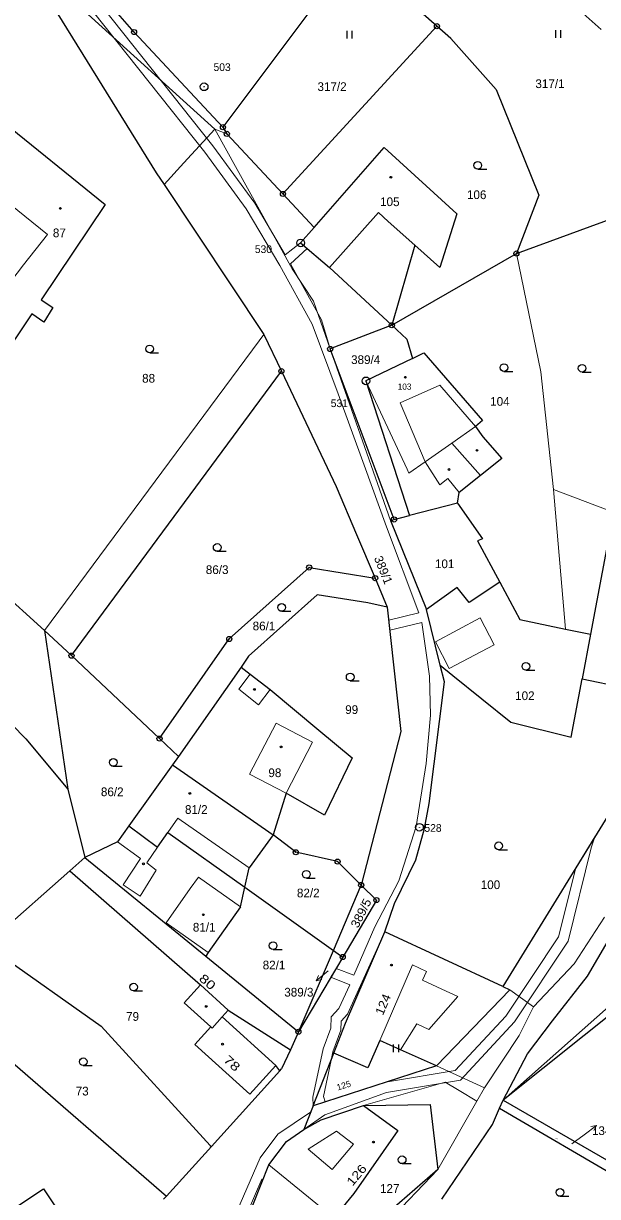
# Model space of a CAD drawing. Extents: x -504006 to -501322, y -1128098 to -1124665.
# Drawn here: x -502691.9 to -502579.9, y -1126531.9 to -1126303.1 of the extents above; entities that cross this region are included whole.
import ezdxf
from ezdxf.enums import TextEntityAlignment as Align

# ---------------------------------------------------------------- set-up
doc = ezdxf.new("R2010")
doc.units = 0
doc.header["$LTSCALE"] = 0.68
for name, color, linetype, lineweight in [('1', 7, 'Continuous', 25), ('13', 7, 'Continuous', 13), ('3', 7, 'Continuous', 25), ('4', 7, 'Continuous', 13), ('5', 7, 'Continuous', 25), ('7', 7, 'Continuous', 13), ('8', 7, 'Continuous', 25)]:
    doc.layers.add(name, color=color, linetype=linetype, lineweight=lineweight)
doc.layers.add('2', color=7, linetype='Continuous')

msp = doc.modelspace()

# ---------------------------------------------------------------- linework, layer by layer
at = {"layer": '1'}
for p, q in [((-502627.56, -1126289.31), (-502653, -1126323.36)), ((-502611.25, -1126303.66), (-502627.56, -1126289.31)), ((-502595.09, -1126290.13), (-502579.17, -1126304.31)), ((-502687.49, -1126297.6), (-502666, -1126332.24)), ((-502670.34, -1126304.81), (-502677, -1126297.14)), ((-502611.25, -1126303.66), (-502641.29, -1126336.37)), ((-502608.55, -1126306.04), (-502611.25, -1126303.66)), ((-502653, -1126323.36), (-502670.34, -1126304.81)), ((-502608.55, -1126306.04), (-502599.68, -1126316.02)), ((-502599.68, -1126316.02), (-502591.34, -1126336.62)), ((-502696.91, -1126321.52), (-502675.99, -1126338.4)), ((-502653, -1126323.36), (-502652.25, -1126324.66)), ((-502641.29, -1126336.37), (-502652.25, -1126324.66)), ((-502635.19, -1126342.89), (-502621.54, -1126327.31)), ((-502621.54, -1126327.31), (-502607.35, -1126340.25)), ((-502666, -1126332.24), (-502664.48, -1126334.52)), ((-502664.48, -1126334.52), (-502644.99, -1126363.8)), ((-502641.29, -1126336.37), (-502635.19, -1126342.89)), ((-502591.34, -1126336.62), (-502595.74, -1126348)), ((-502675.99, -1126338.4), (-502688.46, -1126357.01)), ((-502595.74, -1126348), (-502570.14, -1126338.62)), ((-502607.35, -1126340.25), (-502610.7, -1126350.73)), ((-502635.19, -1126342.89), (-502637.84, -1126345.92)), ((-502637.84, -1126345.92), (-502632.22, -1126350.69)), ((-502615.54, -1126346.39), (-502620.04, -1126361.99)), ((-502620.04, -1126361.99), (-502595.74, -1126348)), ((-502610.7, -1126350.73), (-502615.54, -1126346.39)), ((-502632.22, -1126350.69), (-502620.04, -1126361.99)), ((-502688.46, -1126357.01), (-502686.2, -1126358.53)), ((-502686.2, -1126358.53), (-502687.95, -1126361.35)), ((-502690.31, -1126359.77), (-502697.31, -1126370.22)), ((-502687.95, -1126361.35), (-502690.31, -1126359.77)), ((-502644.99, -1126363.8), (-502641.6, -1126370.94)), ((-502620.04, -1126361.99), (-502632.07, -1126366.61)), ((-502620.04, -1126361.99), (-502617.13, -1126364.69)), ((-502617.13, -1126364.69), (-502616.03, -1126368.48)), ((-502619.62, -1126399.86), (-502632.07, -1126366.61)), ((-502616.03, -1126368.48), (-502625.1, -1126372.83)), ((-502616.03, -1126368.48), (-502613.77, -1126367.39)), ((-502613.77, -1126367.39), (-502602.38, -1126380.59)), ((-502682.55, -1126426.42), (-502641.6, -1126370.94)), ((-502641.6, -1126370.94), (-502630.93, -1126393.44)), ((-502625.1, -1126372.83), (-502616.58, -1126399.09)), ((-502602.38, -1126380.59), (-502603.73, -1126381.76)), ((-502603.73, -1126381.76), (-502602.27, -1126383.76)), ((-502602.27, -1126383.76), (-502598.57, -1126387.94)), ((-502598.57, -1126387.94), (-502602.76, -1126391.31)), ((-502602.76, -1126391.31), (-502606.88, -1126394.62)), ((-502630.93, -1126393.44), (-502626.91, -1126402.76)), ((-502607.25, -1126396.69), (-502606.88, -1126394.62)), ((-502607.25, -1126396.69), (-502616.58, -1126399.09)), ((-502607.25, -1126396.69), (-502602.37, -1126403.63)), ((-502620.31, -1126400.04), (-502619.62, -1126399.86)), ((-502620.31, -1126400.04), (-502613.3, -1126417.44)), ((-502619.62, -1126399.86), (-502616.58, -1126399.09)), ((-502626.91, -1126402.76), (-502623.31, -1126411.3)), ((-502602.37, -1126403.63), (-502603.3, -1126404)), ((-502603.3, -1126404), (-502598.97, -1126412.1)), ((-502577.79, -1126403.55), (-502581.3, -1126422.25)), ((-502705.53, -1126405.59), (-502687.79, -1126421.49)), ((-502651.77, -1126423.17), (-502636.18, -1126409.22)), ((-502636.18, -1126409.22), (-502623.31, -1126411.3)), ((-502623.31, -1126411.3), (-502620.93, -1126416.93)), ((-502598.97, -1126412.1), (-502604.96, -1126416.04)), ((-502598.97, -1126412.1), (-502595.08, -1126419.38)), ((-502634.61, -1126414.54), (-502647.99, -1126426.52)), ((-502624.74, -1126416.13), (-502634.61, -1126414.54)), ((-502607.33, -1126413.1), (-502613.3, -1126417.44)), ((-502604.96, -1126416.04), (-502607.33, -1126413.1)), ((-502620.93, -1126416.93), (-502624.74, -1126416.13)), ((-502716.32, -1126417.67), (-502691.44, -1126442.61)), ((-502620.93, -1126416.93), (-502618.28, -1126441.22)), ((-502610.61, -1126428.26), (-502613.3, -1126417.44)), ((-502595.08, -1126419.38), (-502586.19, -1126421.23)), ((-502586.19, -1126421.23), (-502581.3, -1126422.25)), ((-502687.79, -1126421.49), (-502682.55, -1126426.42)), ((-502687.79, -1126421.49), (-502683.27, -1126452.45)), ((-502665.37, -1126442.59), (-502651.77, -1126423.17)), ((-502581.3, -1126422.25), (-502582.93, -1126430.94)), ((-502665.37, -1126442.59), (-502682.55, -1126426.42)), ((-502647.99, -1126426.52), (-502649.47, -1126428.64)), ((-502610.61, -1126428.26), (-502608.12, -1126430.26)), ((-502609.8, -1126431.52), (-502610.61, -1126428.26)), ((-502649.47, -1126428.64), (-502661.67, -1126446.07)), ((-502649.47, -1126428.64), (-502647.66, -1126430.04)), ((-502647.66, -1126430.04), (-502643.77, -1126433.05)), ((-502608.12, -1126430.26), (-502596.85, -1126439.37)), ((-502612.77, -1126455.27), (-502609.8, -1126431.52)), ((-502585.05, -1126442.3), (-502582.93, -1126430.94)), ((-502582.93, -1126430.94), (-502571.03, -1126433.39)), ((-502643.77, -1126433.05), (-502634.32, -1126440.97)), ((-502596.85, -1126439.37), (-502585.05, -1126442.3)), ((-502634.32, -1126440.97), (-502627.79, -1126446.36)), ((-502618.28, -1126441.22), (-502626.02, -1126471.15)), ((-502691.44, -1126442.61), (-502683.27, -1126452.45)), ((-502661.67, -1126446.07), (-502665.37, -1126442.59)), ((-502661.67, -1126446.07), (-502662.81, -1126447.71)), ((-502627.79, -1126446.36), (-502633.17, -1126457.51)), ((-502662.81, -1126447.71), (-502671.38, -1126459.64)), ((-502662.81, -1126447.71), (-502643.2, -1126461.37)), ((-502573.73, -1126450.8), (-502598.36, -1126490.94)), ((-502683.27, -1126452.45), (-502679.94, -1126465.78)), ((-502640.69, -1126453.24), (-502643.2, -1126461.37)), ((-502633.17, -1126457.51), (-502640.69, -1126453.24)), ((-502613.68, -1126460.12), (-502612.77, -1126455.27)), ((-502671.38, -1126459.64), (-502673.6, -1126462.73)), ((-502671.38, -1126459.64), (-502665.76, -1126463.77)), ((-502615.39, -1126466.27), (-502613.68, -1126460.12)), ((-502665.76, -1126463.77), (-502663.77, -1126460.9)), ((-502663.77, -1126460.9), (-502648.73, -1126471.6)), ((-502643.2, -1126461.37), (-502647.87, -1126467.8)), ((-502638.8, -1126464.76), (-502643.2, -1126461.37)), ((-502673.6, -1126462.73), (-502679.94, -1126465.78)), ((-502630.63, -1126466.58), (-502638.8, -1126464.76)), ((-502679.94, -1126465.78), (-502682.88, -1126468.4)), ((-502679.94, -1126465.78), (-502656.37, -1126485)), ((-502619.54, -1126474.74), (-502615.39, -1126466.27)), ((-502682.88, -1126468.4), (-502699.2, -1126482.81)), ((-502682.88, -1126468.4), (-502657.37, -1126490.63)), ((-502648.73, -1126471.6), (-502647.87, -1126467.8)), ((-502649.59, -1126475.4), (-502648.73, -1126471.6)), ((-502648.73, -1126471.6), (-502631.46, -1126483.89)), ((-502626.02, -1126471.15), (-502623.06, -1126474.09)), ((-502649.59, -1126475.4), (-502655.87, -1126484.28)), ((-502623.06, -1126474.09), (-502629.63, -1126485.19)), ((-502621.42, -1126480.31), (-502619.54, -1126474.74)), ((-502581.9, -1126488.91), (-502575.83, -1126478.59)), ((-502629.06, -1126498.08), (-502621.42, -1126480.31)), ((-502598.36, -1126490.94), (-502621.42, -1126480.31)), ((-502699.2, -1126482.81), (-502676.74, -1126498.71)), ((-502655.87, -1126484.28), (-502656.37, -1126485)), ((-502656.37, -1126485), (-502638.27, -1126499.77)), ((-502637.74, -1126498.61), (-502631.46, -1126483.89)), ((-502561.92, -1126484.04), (-502598.32, -1126513.14)), ((-502588.67, -1126497.67), (-502581.9, -1126488.91)), ((-502709.81, -1126492.11), (-502664.03, -1126531.82)), ((-502660.55, -1126494.14), (-502657.37, -1126490.63)), ((-502657.37, -1126490.63), (-502651.96, -1126495.53)), ((-502597.01, -1126491.58), (-502611.34, -1126506.44)), ((-502598.36, -1126490.94), (-502597.01, -1126491.58)), ((-502655.36, -1126498.84), (-502660.55, -1126494.14)), ((-502676.74, -1126498.71), (-502655.49, -1126521.94)), ((-502658.46, -1126502.28), (-502655.36, -1126498.84)), ((-502638.27, -1126499.77), (-502637.74, -1126498.61)), ((-502631.36, -1126503.97), (-502629.06, -1126498.08)), ((-502593.59, -1126504.1), (-502588.67, -1126497.67)), ((-502638.27, -1126499.77), (-502639.85, -1126503.27)), ((-502622.42, -1126501.48), (-502624.74, -1126506.83)), ((-502618.36, -1126503.3), (-502622.42, -1126501.48)), ((-502647.75, -1126511.97), (-502658.46, -1126502.28)), ((-502611.34, -1126506.44), (-502618.36, -1126503.3)), ((-502635.4, -1126514.21), (-502631.36, -1126503.97)), ((-502624.74, -1126506.83), (-502631.36, -1126503.97)), ((-502598.32, -1126513.14), (-502593.59, -1126504.1)), ((-502655.26, -1126522.15), (-502641.92, -1126507.41)), ((-502642.67, -1126506.35), (-502647.75, -1126511.97)), ((-502641.92, -1126507.41), (-502642.67, -1126506.35)), ((-502641.92, -1126507.41), (-502641.56, -1126507.02)), ((-502611.34, -1126506.44), (-502635.4, -1126514.21)), ((-502635.4, -1126514.21), (-502637.23, -1126518.86)), ((-502633.86, -1126516.95), (-502625.57, -1126514.13)), ((-502625.57, -1126514.13), (-502612.58, -1126513.94)), ((-502625.57, -1126514.13), (-502618.86, -1126519.01)), ((-502612.58, -1126513.94), (-502611.07, -1126526.63)), ((-502600.43, -1126517.88), (-502599.01, -1126514.68)), ((-502599.01, -1126514.68), (-502598.32, -1126513.14)), ((-502599.01, -1126514.68), (-502569.59, -1126531.9)), ((-502598.32, -1126513.14), (-502568.21, -1126530.47)), ((-502637.23, -1126518.86), (-502633.86, -1126516.95)), ((-502640.6, -1126521.19), (-502637.23, -1126518.86)), ((-502618.86, -1126519.01), (-502627.44, -1126531.29)), ((-502610.27, -1126532.43), (-502600.43, -1126517.88)), ((-502655.49, -1126521.94), (-502655.26, -1126522.15)), ((-502644.02, -1126525.7), (-502640.6, -1126521.19)), ((-502664.03, -1126531.82), (-502655.26, -1126522.15)), ((-502649.16, -1126538.63), (-502644.02, -1126525.7)), ((-502611.07, -1126526.63), (-502637.57, -1126549.58)), ((-502664.57, -1126532.42), (-502664.03, -1126531.82)), ((-502627.44, -1126531.29), (-502631.37, -1126536.07))]:
    msp.add_line(p, q, dxfattribs=at)
for points in [[(-502631.46, -1126483.89), (-502626.02, -1126471.15), (-502630.63, -1126466.58)], [(-502631.46, -1126483.89), (-502629.63, -1126485.19), (-502638.27, -1126499.77)], [(-502651.96, -1126495.53), (-502639.85, -1126503.27), (-502641.56, -1126507.02)], [(-502693.42, -1126533.96), (-502688, -1126530.4), (-502679.7, -1126542.9), (-502681.26, -1126543.91)]]:
    msp.add_lwpolyline(points, dxfattribs=at)
at = {"layer": '13'}
for points in [[(-502645.17, -1126528.59), (-502644.02, -1126525.7), (-502640.6, -1126521.19), (-502637.23, -1126518.86), (-502633.09, -1126516), (-502621.11, -1126511.59), (-502606.66, -1126509.2), (-502596.12, -1126497.84), (-502585.64, -1126482.1), (-502581.13, -1126463.89), (-502580.44, -1126461.74), (-502584.15, -1126467.79), (-502587.5, -1126481.28), (-502597.78, -1126496.73), (-502607.66, -1126507.34), (-502620.91, -1126509.53), (-502633.05, -1126513.45), (-502633.41, -1126512.39), (-502631.89, -1126505.32), (-502631.54, -1126503.66), (-502630, -1126499.45), (-502629.9, -1126497.68), (-502628.69, -1126496.37), (-502621.42, -1126480.31), (-502619.54, -1126474.74), (-502615.39, -1126466.27), (-502613.68, -1126460.12), (-502612.77, -1126455.27), (-502609.8, -1126431.52), (-502610.61, -1126428.26), (-502613.3, -1126417.44), (-502620.31, -1126400.04), (-502619.62, -1126399.86), (-502632.07, -1126366.61), (-502633.75, -1126360.95), (-502639.8, -1126350.02), (-502636.58, -1126346.99), (-502637.84, -1126345.92), (-502640.83, -1126348.25), (-502646.79, -1126338.19), (-502654.98, -1126327), (-502676.64, -1126299.73)], [(-502678.26, -1126300.91), (-502656.56, -1126328.22), (-502648.47, -1126339.29), (-502641.92, -1126350.33), (-502635.57, -1126361.79), (-502630.55, -1126375.37), (-502625.43, -1126389.25), (-502621.1, -1126401.27), (-502614.75, -1126418.05), (-502620.65, -1126419.47), (-502620.43, -1126421.47), (-502614.22, -1126419.98), (-502612.67, -1126430.45), (-502612.49, -1126438.01), (-502613.33, -1126447.45), (-502615.27, -1126459.72), (-502618.66, -1126470.31), (-502623.34, -1126479.33), (-502627.45, -1126488.75), (-502630.94, -1126487.41), (-502631.98, -1126489.15), (-502628.25, -1126490.59), (-502630.37, -1126495.25), (-502631.86, -1126496.84), (-502631.98, -1126499.05), (-502633.46, -1126503.1), (-502635.47, -1126512.51), (-502635.4, -1126514.21), (-502635.9, -1126515.48), (-502642.28, -1126519.77), (-502645.75, -1126524.36), (-502651.61, -1126537.8)], [(-502649.91, -1126538.89), (-502645.38, -1126528.51), (-502645.17, -1126528.59)]]:
    msp.add_lwpolyline(points, dxfattribs=at)
at = {"layer": '3'}
for p, q in [((-502628.781, -1126306.05), (-502628.781, -1126304.55)), ((-502627.78, -1126306.05), (-502627.78, -1126304.55)), ((-502588.061, -1126305.96), (-502588.061, -1126304.46)), ((-502587.06, -1126305.96), (-502587.06, -1126304.46)), ((-502603.283, -1126331.55), (-502601.533, -1126331.55)), ((-502667.293, -1126367.35), (-502665.543, -1126367.35)), ((-502598.163, -1126370.98), (-502596.413, -1126370.98)), ((-502582.923, -1126371.11), (-502581.173, -1126371.11)), ((-502654.123, -1126406.07), (-502652.373, -1126406.07)), ((-502641.533, -1126417.77), (-502639.783, -1126417.77)), ((-502593.883, -1126429.26), (-502592.133, -1126429.26)), ((-502628.173, -1126431.34), (-502626.423, -1126431.34)), ((-502674.393, -1126448), (-502672.643, -1126448)), ((-502599.213, -1126464.26), (-502597.463, -1126464.26)), ((-502636.723, -1126469.81), (-502634.973, -1126469.81)), ((-502643.213, -1126483.72), (-502641.463, -1126483.72)), ((-502670.433, -1126491.81), (-502668.683, -1126491.81)), ((-502619.711, -1126503.75), (-502619.711, -1126502.25)), ((-502618.71, -1126503.75), (-502618.71, -1126502.25)), ((-502680.253, -1126506.37), (-502678.503, -1126506.37)), ((-502618.033, -1126525.49), (-502616.283, -1126525.49)), ((-502587.233, -1126531.86), (-502585.483, -1126531.86))]:
    msp.add_line(p, q, dxfattribs=at)
for centre in [(-502603.2829, -1126330.7998), (-502667.2929, -1126366.5998), (-502598.1629, -1126370.2298), (-502582.9229, -1126370.3598), (-502654.1229, -1126405.3198), (-502641.5329, -1126417.0198), (-502593.8829, -1126428.5098), (-502628.1729, -1126430.5898), (-502674.3929, -1126447.2498), (-502599.2129, -1126463.5098), (-502636.7229, -1126469.0598), (-502643.2129, -1126482.9698), (-502670.4329, -1126491.0598), (-502680.2529, -1126505.6198), (-502618.0329, -1126524.7398), (-502587.2329, -1126531.1098)]:
    msp.add_circle(centre, 0.75, dxfattribs=at)
at = {"layer": '4'}
for p, q in [((-502680.04, -1126300.71), (-502654.57, -1126323.71)), ((-502654.57, -1126323.71), (-502660.62, -1126330.31)), ((-502654.57, -1126323.71), (-502639.5, -1126350.98)), ((-502652.25, -1126324.66), (-502654.57, -1126323.71)), ((-502660.62, -1126330.31), (-502664.48, -1126334.52)), ((-502687.21, -1126344.31), (-502696.05, -1126337.11)), ((-502622.66, -1126340), (-502632.22, -1126350.69)), ((-502620.74, -1126341.72), (-502622.66, -1126340)), ((-502615.54, -1126346.39), (-502620.74, -1126341.72)), ((-502691.91, -1126350.23), (-502687.21, -1126344.31)), ((-502590.98, -1126371.05), (-502595.74, -1126348)), ((-502699.53, -1126360.17), (-502691.91, -1126350.23)), ((-502639.5, -1126350.98), (-502635.34, -1126357.31)), ((-502632.07, -1126366.61), (-502635.34, -1126357.31)), ((-502644.99, -1126363.8), (-502645.91, -1126364.99)), ((-502645.91, -1126364.99), (-502687.79, -1126421.49)), ((-502632.07, -1126366.61), (-502620.31, -1126400.04)), ((-502588.48, -1126394.04), (-502590.98, -1126371.05)), ((-502625.1, -1126372.83), (-502617.05, -1126390.08)), ((-502610.69, -1126373.65), (-502618.44, -1126377.1)), ((-502603.73, -1126381.76), (-502610.69, -1126373.65)), ((-502618.44, -1126377.1), (-502613.55, -1126388.6)), ((-502613.55, -1126388.6), (-502608.37, -1126384.99)), ((-502613.55, -1126388.6), (-502616.72, -1126390.8)), ((-502616.72, -1126390.8), (-502617.05, -1126390.08)), ((-502588.48, -1126394.04), (-502586.19, -1126421.23)), ((-502578.06, -1126397.97), (-502588.48, -1126394.04)), ((-502611.54, -1126423.71), (-502602.8, -1126419.06)), ((-502602.8, -1126419.06), (-502600.07, -1126424.33)), ((-502608.84, -1126428.92), (-502611.54, -1126423.71)), ((-502600.07, -1126424.33), (-502608.84, -1126428.92)), ((-502649.93, -1126432.97), (-502647.66, -1126430.04)), ((-502646.03, -1126435.98), (-502649.93, -1126432.97)), ((-502643.77, -1126433.05), (-502646.03, -1126435.98)), ((-502647.79, -1126449.56), (-502642.62, -1126439.6)), ((-502642.62, -1126439.6), (-502635.52, -1126443.28)), ((-502635.52, -1126443.28), (-502640.69, -1126453.24)), ((-502640.69, -1126453.24), (-502647.79, -1126449.56)), ((-502663.77, -1126460.9), (-502661.83, -1126458.12)), ((-502647.87, -1126467.8), (-502661.83, -1126458.12)), ((-502669.08, -1126465.98), (-502673.6, -1126462.73)), ((-502665.76, -1126463.77), (-502667.88, -1126466.82)), ((-502672.47, -1126471.1), (-502669.08, -1126465.98)), ((-502667.88, -1126466.82), (-502666, -1126468.28)), ((-502666, -1126468.28), (-502669.17, -1126473.31)), ((-502669.17, -1126473.31), (-502672.47, -1126471.1)), ((-502659.37, -1126471.85), (-502657.79, -1126469.61)), ((-502657.79, -1126469.61), (-502649.59, -1126475.4)), ((-502664.06, -1126478.5), (-502659.37, -1126471.85)), ((-502655.87, -1126484.28), (-502664.06, -1126478.5)), ((-502584.47, -1126486.55), (-502578.58, -1126477.39)), ((-502598.32, -1126513.14), (-502563.94, -1126482.57)), ((-502616.04, -1126486.73), (-502622.42, -1126501.48)), ((-502613.26, -1126488.03), (-502616.04, -1126486.73)), ((-502592.41, -1126494.88), (-502584.47, -1126486.55)), ((-502614.04, -1126489.68), (-502613.26, -1126488.03)), ((-502610.28, -1126491.45), (-502614.04, -1126489.68)), ((-502607.19, -1126492.91), (-502610.28, -1126491.45)), ((-502597.01, -1126491.58), (-502592.41, -1126494.88)), ((-502612.83, -1126499.32), (-502607.19, -1126492.91)), ((-502655.13, -1126499.05), (-502653.16, -1126496.86)), ((-502651.96, -1126495.53), (-502653.16, -1126496.86)), ((-502653.16, -1126496.86), (-502642.67, -1126506.35)), ((-502595.17, -1126500.5), (-502592.41, -1126494.88)), ((-502655.36, -1126498.84), (-502655.13, -1126499.05)), ((-502618.36, -1126503.3), (-502615.2, -1126498.25)), ((-502615.2, -1126498.25), (-502612.83, -1126499.32)), ((-502601.99, -1126510.71), (-502595.17, -1126500.5)), ((-502611.34, -1126506.44), (-502601.99, -1126510.71)), ((-502609.67, -1126509.57), (-502625.57, -1126514.13)), ((-502606.94, -1126511.23), (-502609.67, -1126509.57)), ((-502603.48, -1126513.33), (-502606.94, -1126511.23)), ((-502603.48, -1126513.33), (-502601.99, -1126510.71)), ((-502611.07, -1126526.63), (-502603.48, -1126513.33)), ((-502634.96, -1126521.78), (-502630.87, -1126519.13)), ((-502630.87, -1126519.13), (-502627.5, -1126521.66)), ((-502636.37, -1126522.69), (-502634.96, -1126521.78)), ((-502627.5, -1126521.66), (-502631.71, -1126526.64)), ((-502631.71, -1126526.64), (-502636.37, -1126522.69)), ((-502631.37, -1126536.07), (-502644.02, -1126525.7)), ((-502626.84, -1126543.07), (-502611.07, -1126526.63))]:
    msp.add_line(p, q, dxfattribs=at)
for points in [[(-502602.76, -1126391.31), (-502608.37, -1126384.99), (-502603.73, -1126381.76)], [(-502606.88, -1126394.62), (-502609.09, -1126391.86), (-502610.65, -1126393.11), (-502613.55, -1126388.6)]]:
    msp.add_lwpolyline(points, dxfattribs=at)
at = {"layer": '5'}
for centre in [(-502620.2468, -1126333.1192), (-502684.7268, -1126339.1892), (-502617.4068, -1126372.1292), (-502603.4268, -1126386.3792), (-502608.8968, -1126390.1192), (-502646.8568, -1126432.9992), (-502641.6568, -1126444.2192), (-502659.4668, -1126453.2792), (-502668.5268, -1126467.0092), (-502656.8268, -1126476.9392), (-502620.1268, -1126486.7592), (-502656.2568, -1126494.8292), (-502653.0668, -1126502.1992), (-502623.6368, -1126521.2792)]:
    msp.add_circle(centre, 0.175, dxfattribs=at)
at = {"layer": '7'}
for p, q in [((-502634.779, -1126489.829), (-502633.69, -1126489.569)), ((-502580.133, -1126518.034), (-502581.234, -1126518.237))]:
    msp.add_line(p, q, dxfattribs=at)
for points in [[(-502632.48, -1126487.9), (-502634.779, -1126489.829), (-502634.334, -1126488.802)], [(-502584.95, -1126521.63), (-502582.53, -1126519.84), (-502580.133, -1126518.034), (-502580.632, -1126519.037)]]:
    msp.add_lwpolyline(points, dxfattribs=at)
at = {"layer": '8'}
for centre, radius in [((-502670.34, -1126304.8099), 0.5), ((-502611.25, -1126303.6599), 0.5), ((-502611.25, -1126303.6599), 0.0303), ((-502670.34, -1126304.8099), 0.0303), ((-502656.67, -1126315.4798), 0.75), ((-502656.67, -1126315.4798), 0.03), ((-502653, -1126323.3599), 0.5), ((-502653, -1126323.3599), 0.0303), ((-502652.25, -1126324.6599), 0.5), ((-502652.25, -1126324.6599), 0.0303), ((-502641.29, -1126336.3699), 0.5), ((-502641.29, -1126336.3699), 0.0303), ((-502637.84, -1126345.9198), 0.75), ((-502637.84, -1126345.9198), 0.03), ((-502595.74, -1126347.9999), 0.5), ((-502595.74, -1126347.9999), 0.0303), ((-502620.04, -1126361.9899), 0.5), ((-502620.04, -1126361.9899), 0.0303), ((-502632.07, -1126366.6099), 0.5), ((-502632.07, -1126366.6099), 0.0303), ((-502641.6, -1126370.9399), 0.5), ((-502641.6, -1126370.9399), 0.0303), ((-502625.1, -1126372.8298), 0.75), ((-502625.1, -1126372.8298), 0.03), ((-502619.62, -1126399.8599), 0.5), ((-502619.62, -1126399.8599), 0.0303), ((-502636.18, -1126409.2199), 0.5), ((-502636.18, -1126409.2199), 0.0303), ((-502623.31, -1126411.2999), 0.5), ((-502623.31, -1126411.2999), 0.0303), ((-502651.77, -1126423.1699), 0.5), ((-502651.77, -1126423.1699), 0.0303), ((-502682.55, -1126426.4199), 0.5), ((-502682.55, -1126426.4199), 0.0303), ((-502665.37, -1126442.5899), 0.5), ((-502665.37, -1126442.5899), 0.0303), ((-502614.65, -1126459.8898), 0.75), ((-502614.65, -1126459.8898), 0.03), ((-502638.8, -1126464.7599), 0.5), ((-502638.8, -1126464.7599), 0.0303), ((-502630.63, -1126466.5799), 0.5), ((-502630.63, -1126466.5799), 0.0303), ((-502626.02, -1126471.1499), 0.5), ((-502626.02, -1126471.1499), 0.0303), ((-502623.06, -1126474.0899), 0.5), ((-502623.06, -1126474.0899), 0.0303), ((-502629.63, -1126485.1899), 0.5), ((-502629.63, -1126485.1899), 0.0303), ((-502638.27, -1126499.7699), 0.5), ((-502638.27, -1126499.7699), 0.0303)]:
    msp.add_circle(centre, radius, dxfattribs=at)

# ---------------------------------------------------------------- texts
at = {"layer": '2'}
for s, height, p in [('317/2', 1.7, (-502631.71, -1126316.295)), ('317/1', 1.7, (-502589.19, -1126315.725)), ('106', 1.7, (-502603.489, -1126337.375)), ('105', 1.7, (-502620.439, -1126338.745)), ('87', 1.7, (-502684.919, -1126344.815)), ('389/4', 1.7, (-502625.15, -1126369.545)), ('88', 1.7, (-502667.509, -1126373.175)), ('103', 1.2, (-502617.559, -1126374.55)), ('104', 1.7, (-502598.959, -1126377.685)), ('101', 1.7, (-502609.739, -1126409.355)), ('86/3', 1.7, (-502654.129, -1126410.502)), ('86/1', 1.7, (-502644.989, -1126421.485)), ('102', 1.7, (-502594.089, -1126435.085)), ('99', 1.7, (-502627.879, -1126437.795)), ('98', 1.7, (-502642.869, -1126450.105)), ('86/2', 1.7, (-502674.599, -1126453.825)), ('81/2', 1.7, (-502658.199, -1126457.275)), ('82/2', 1.7, (-502636.349, -1126473.555)), ('100', 1.7, (-502600.799, -1126471.945)), ('81/1', 1.7, (-502656.659, -1126480.235)), ('82/1', 1.7, (-502643.029, -1126487.605)), ('79', 1.7, (-502670.639, -1126497.635)), ('73', 1.7, (-502680.459, -1126512.195)), ('127', 1.7, (-502620.459, -1126531.185))]:
    msp.add_text(s, height=height, dxfattribs=at).set_placement(p, align=Align.CENTER)
msp.add_text('389/1', height=1.7, rotation=292, dxfattribs=at).set_placement((-502622.4881, -1126410.0306), align=Align.CENTER)
for s, height, rotation, width, p in [('389/5', 1.7, 63, 1.05, (-502625.3003, -1126477.0254)), ('80', 1.7, 319, 1.3, (-502656.5746, -1126490.6869)), ('124', 1.7, 67, 1.1, (-502620.9763, -1126494.7761)), ('78', 1.7, 318, 1.3, (-502651.8048, -1126506.5561)), ('125', 1.2, 17, 1.05, (-502629.2524, -1126510.8195)), ('134', 0.2, 329, 1.1, (-502587.9695, -1126520.6881)), ('126', 1.7, 50, 1.2, (-502626.2702, -1126528.2644))]:
    msp.add_text(s, height=height, rotation=rotation, dxfattribs=dict(at, width=width)).set_placement(p, align=Align.CENTER)
msp.add_text('389/3', height=1.7, dxfattribs=at).set_placement((-502635.34, -1126492.905), align=Align.RIGHT)
msp.add_text('134', height=1.7, dxfattribs=at).set_placement((-502581, -1126519.915))
at = {"layer": '8'}
for s, p in [('503', (-502651.489, -1126312.395)), ('530', (-502643.429, -1126347.895)), ('531', (-502628.619, -1126377.945)), ('528', (-502610.339, -1126460.775))]:
    msp.add_text(s, height=1.5, dxfattribs=at).set_placement(p, align=Align.RIGHT)

doc.saveas('drawing.dxf')
